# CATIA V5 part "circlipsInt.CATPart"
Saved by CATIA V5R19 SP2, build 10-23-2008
Part number: circlipsInt
Definition: NONE
Nomenclature: 1
Source: Unknown
Description: PART-1-DESC
Bounding box of the stored display mesh (mm): x -29.5 to 29.5, y -29.429 to 29.5, z 0 to 2
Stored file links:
  D:\SCHOOL\FRANCE\BANC_POUTRE_EN_MOUSSE\circlipsInt.CATPart
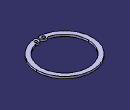
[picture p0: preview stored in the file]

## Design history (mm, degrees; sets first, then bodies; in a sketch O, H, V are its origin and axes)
Body1 "1" (main body)
  Solid1: solid without history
